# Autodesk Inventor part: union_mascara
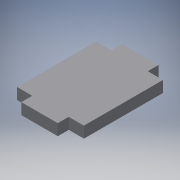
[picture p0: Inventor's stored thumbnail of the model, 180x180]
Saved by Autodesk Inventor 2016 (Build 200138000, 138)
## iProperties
Created: 2017-06
Part Number: union_mascara
Material: Generic
Document SubType Name: Modeling
Designer: laboratorioesan
Density: 1 g/cm^3
Appearance: Default
Author: laboratorioesan
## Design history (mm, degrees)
sketch "Sketch1"
  geometry: L1 (0, 0)-(60, 0) reference; L2 (0, 0)-(0, -18.5) reference; L3 (60, -18.5)-(0, -18.5) reference; L4 (60, 0)-(60, -18.5) reference; L5 (0, -148.5)-(60, -148.5) reference; L6 (0, -148.5)-(0, -167) reference; L7 (60, -167)-(0, -167) reference; L8 (60, -148.5)-(60, -167) reference; L9 (-25, -18.5)-(85, -18.5); L10 (85, -18.5)-(85, -148.5); L11 (85, -148.5)-(-25, -148.5); L12 (-25, -148.5)-(-25, -18.5); L13 (0, -18.5)-(60, -18.5); L14 (60, -18.5)-(60, -0.5); L15 (60, -0.5)-(0, -0.5); L16 (0, -0.5)-(0, -18.5); L17 (0, -148.5)-(60, -148.5); L18 (60, -148.5)-(60, -166.5); L19 (60, -166.5)-(0, -166.5); L20 (0, -166.5)-(0, -148.5)
  constraints: 24 end point, 6 parallel, 3 horizontal, 3 perpendicular, 2 point on line
  dimensions: "d0" = 18 distance of L14.end L13.end; "d1" = 18 distance of L17.end L18.end; "d2" = 25 distance of L2.end L9.start; "d3" = 25 distance of L9.end L3.start
extrude "Extrusion1" new body sketch "Sketch1" distance "d4" = 18.5; taper "d5" = 0 deg
body "Solid1"
node "Reference1"
node "Reference2"
